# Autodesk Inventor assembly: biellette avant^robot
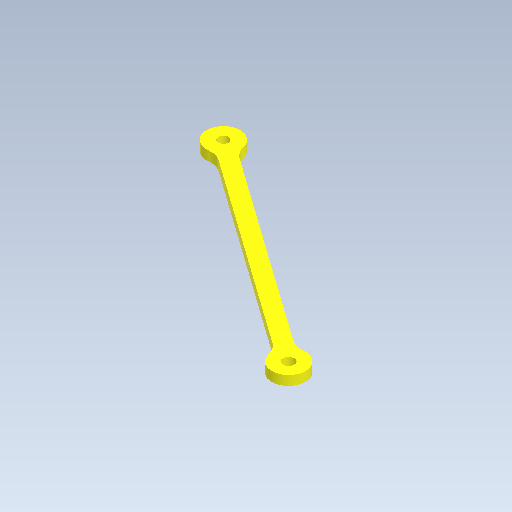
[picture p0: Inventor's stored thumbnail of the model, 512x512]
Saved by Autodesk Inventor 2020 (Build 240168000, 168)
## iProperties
Created: 2018-10
Part Number: biellette avant^robot
Document SubType Name: Assembly
Designer: bruno
Sending System: SolidWorks 2016
Last Author: Prof
Last Saved: 2018-10-03
Author: bruno
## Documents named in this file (2)
- C:\Users\bruno\Documents\Systèmes\Mallette Bras robotisé (273265)\Dossier ressources\Maquette Dobot SW2016\biellette avant^robot.iam
- C:\Users\bruno\Documents\Systèmes\Mallette Bras robotisé (273265)\Dossier ressources\Maquette Dobot SW2016\______33_A.ipt
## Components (1 placed, 1 different names)
1. ______33_A:1
